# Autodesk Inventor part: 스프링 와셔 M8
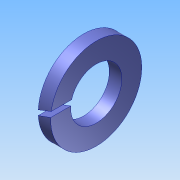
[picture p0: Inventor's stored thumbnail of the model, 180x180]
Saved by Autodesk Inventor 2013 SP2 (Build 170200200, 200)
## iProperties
Created: 2025-10
Part Number: 스프링 와셔 M8
Material: Generic
Document SubType Name: Modeling
Designer: a
Density: 1 g/cm^3
Author: a
변환 표준: STEP AP214IS
전처리기: Build: 200, Release: 2013 SP2 Update 6 - Date: Thu 07/17/2014
전송 단위: 밀리미터
불확실성: 0.01
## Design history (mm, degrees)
node "스프링 와셔 M81"
body "Solid1"
node "기준1"
